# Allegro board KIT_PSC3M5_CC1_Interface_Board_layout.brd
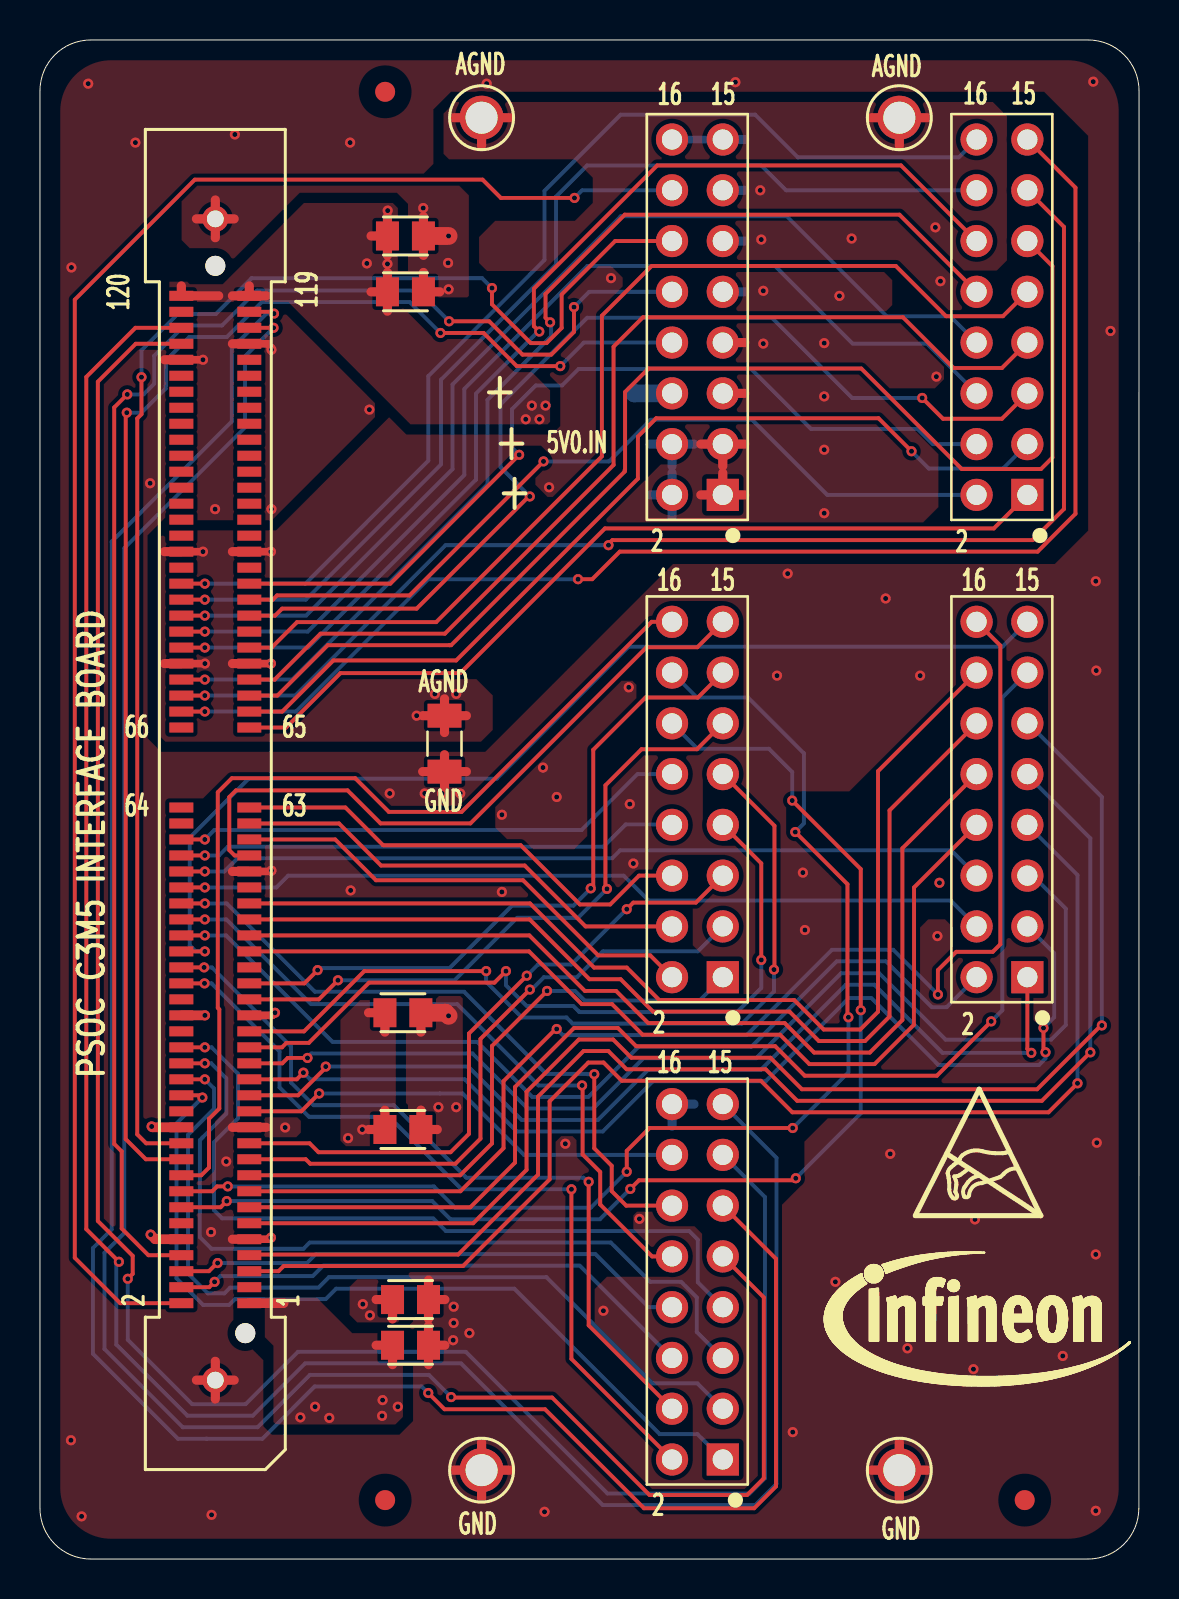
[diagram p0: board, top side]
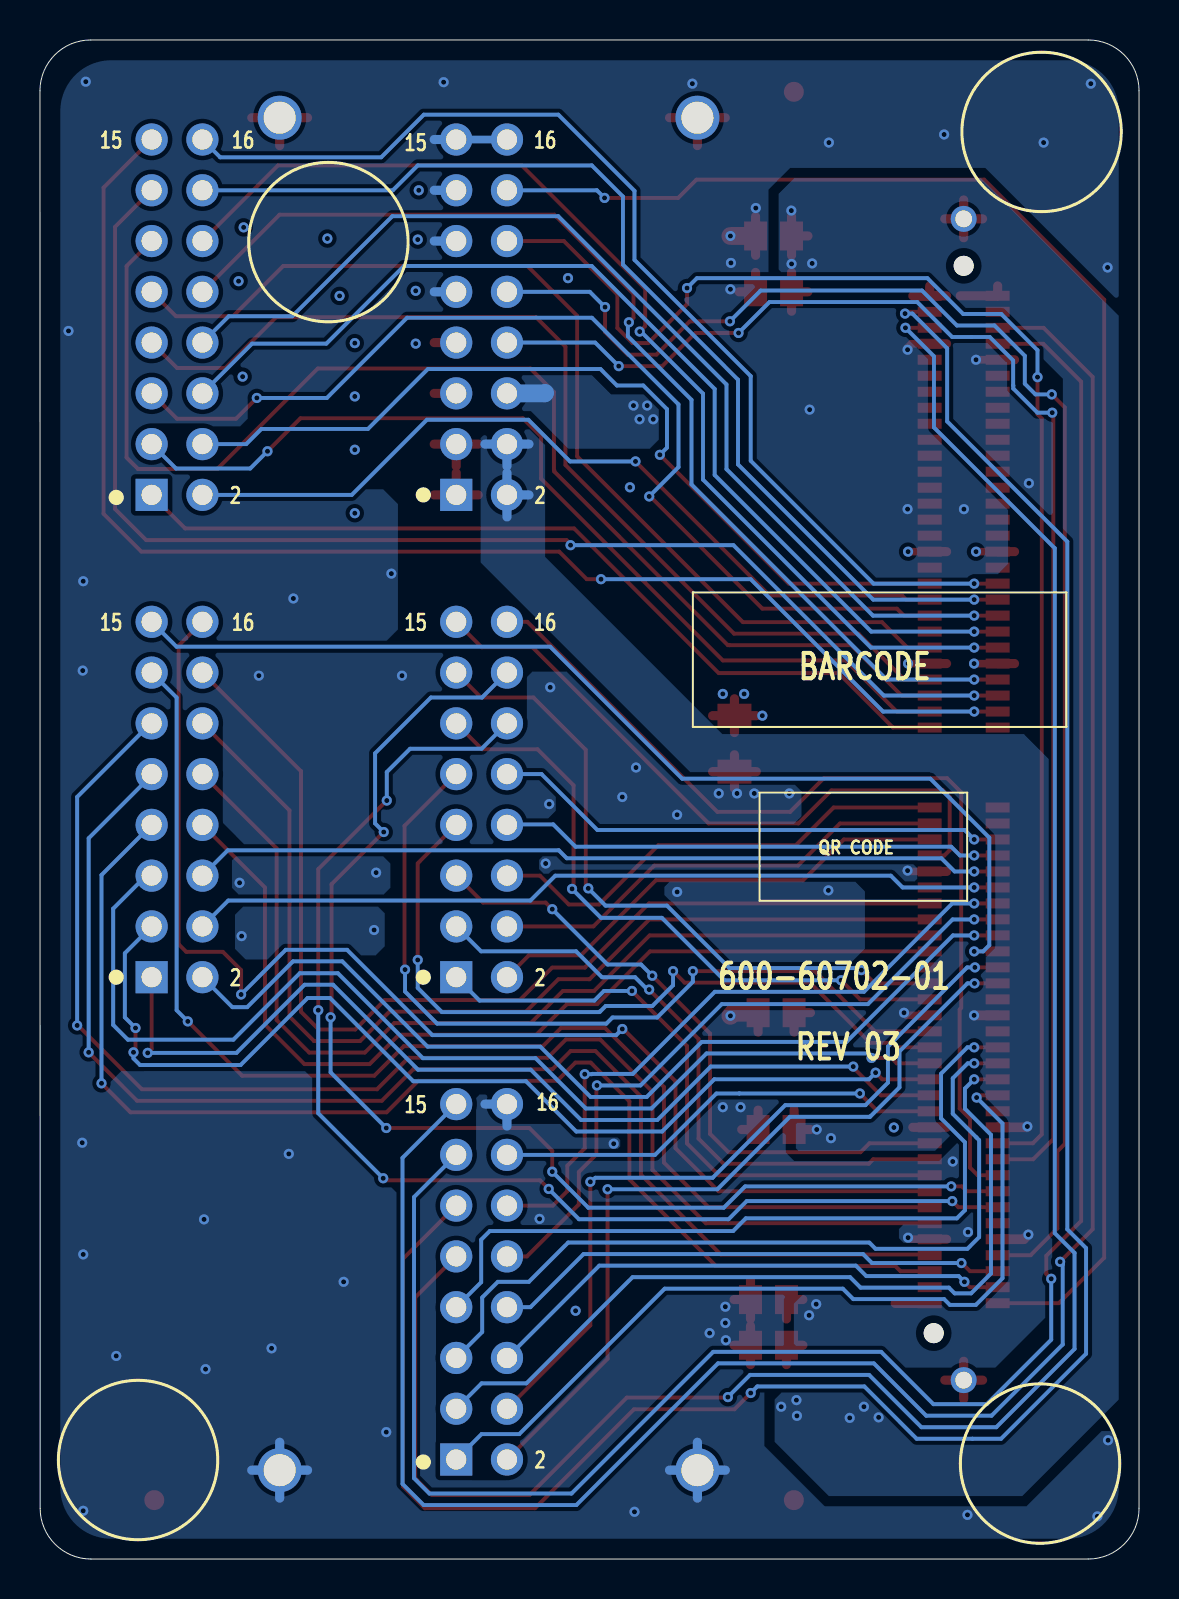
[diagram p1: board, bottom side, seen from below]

Outline 55 x 76 mm; copper layers: TOP, GND, GND1, BOTTOM. Coordinates in mm from the lower left corner of the outline.
Outline path: 0,73.46 0,2.54 arc(0.74,0.74) 2.54,0 52.45,0 arc(54.24,0.74) 54.99,2.54 55,73.46 arc(54.25,75.26) 52.46,76 2.54,76 arc(0.74,75.26) 0,73.46

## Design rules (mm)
constraint set DEFAULT: min track width 0.196

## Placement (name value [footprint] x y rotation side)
C1  0.1uF  [CAPC2012_0805N]  18.29 66.19 0 top
C2  0.1uF  [CAPC2012_0805N]  18.29 63.4 0 top
C3  0.1uF  [CAPC2012_0805N]  18.54 10.69 0 top
C4  0.1uF  [CAPC2012_0805N]  18.16 27.33 0 top
C5  0.1uF  [CAPC2012_0805N]  18.16 21.49 0 top
C6  0.1uF  [CAPC2012_0805N]  18.54 12.98 0 top
J1  HSEC8-160-01-L-DV-A-BL  [SAMTEC_HSEC8-160-01-L-DV-A-BL]  8.77 38 90 top
J2  HDR 8x2  [CTST254P2X08_W515]  34.17 4.98 90 top
J3  HDR 8x2  [CTST254P2X08_W515]  49.41 29.11 90 top
J4  HDR 8x2  [CTST254P2X08_W515]  34.17 29.11 90 top
J5  HDR 8x2  [CTST254P2X08_W515]  34.17 53.24 90 top
J6  HDR 8x2  [CTST254P2X08_W515]  49.41 53.24 90 top
NOREF  -  []  23.53 72.82 0 top
NOREF#2  -  []  -33.32 26.75 0 top
NOREF#3  -  []  7.07 12.8 90 top
NOREF#4  -  []  23.53 5.16 0 top
NOREF#5  -  []  5.27 71.52 0 top
NOREF#6  -  []  8.77 64.7 0 top
NOREF#7  -  [unnamed#2]  17.27 2.95 0 top
NOREF#8  -  []  124 82.91 0 top
NOREF#9  -  []  44.44 5.16 0 top
NOREF#10  -  []  0 2.54 0 top
NOREF#11  -  [unnamed#2]  17.27 73.41 0 top
NOREF#12  -  []  7.07 63.2 0 top
NOREF#13  -  []  -287.97 -199.2 0 top
NOREF#14  -  []  8.77 8.95 90 top
NOREF#15  -  []  166.42 292.69 0 top
NOREF#16  -  []  54.38 75.12 0 top
NOREF#17  -  []  2.54 0 90 top
NOREF#18  -  []  44.44 72.82 0 top
NOREF#19  -  []  7.07 41.6 90 top
NOREF#20  -  []  7.07 37.6 90 top
NOREF#21  -  []  8.77 8.95 90 top
NOREF#22  -  []  -32.82 -22.43 0 top
NOREF#23  -  []  5.27 4.47 90 top
NOREF#24  -  [unnamed#2]  49.28 2.95 0 top
R1  0 OHM  [RESC3216_1206N]  20.24 40.79 90 top
TP1  BLACK  [TPT_KEY_5011]  43 4.45 0 top
TP2  BLACK  [TPT_KEY_5011]  22.1 4.45 0 top
TP3  BLACK  [TPT_KEY_5011]  22.1 72.11 0 top
TP4  BLACK  [TPT_KEY_5011]  43 72.11 0 top

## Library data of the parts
C1-C6 = CAP-NP
J1 = SKT-120-ODD-EVEN-HSEC8-2SH-J
J2-J6 = PLG-16-ODD-EVEN-J
R1 = RES: User Part Number: Part No
TP1-TP4 = TP

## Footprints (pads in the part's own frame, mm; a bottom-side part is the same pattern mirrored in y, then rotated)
CAPC2012_0805N
  rect 1.15x1.45 smd: 1(-0.9,0) 2(0.9,0)
CTST254P2X08_W515
  rect 1.61x1.61 hole 1.01: 1(0,0)
  round 1.61 hole 1.01: 2(0,2.54) 3(2.54,0) 4(2.54,2.54) 5(5.08,0) 6(5.08,2.54) 7(7.62,0) 8(7.62,2.54) 9(10.16,0) 10(10.16,2.54) 11(12.7,0) 12(12.7,2.54) 13(15.24,0) 14(15.24,2.54) 15(17.78,0) 16(17.78,2.54)
RESC3216_1206N
  rect 1.2x1.7 smd: 1(-1.4,0) 2(1.4,0)
SAMTEC_HSEC8-160-01-L-DV-A-BL
  round 1 hole 1.27 unplated: (-26.7,-1.5) (26.7,0)
  rect 0.5x1.2 smd: 1(-25.2,-1.7) 2(-25.2,1.7) 3(-24.4,-1.7) 4(-24.4,1.7) 5(-23.6,-1.7) 6(-23.6,1.7) 7(-22.8,-1.7) 8(-22.8,1.7) 9(-22,-1.7) 10(-22,1.7) 11(-21.2,-1.7) 12(-21.2,1.7) 13(-20.4,-1.7) 14(-20.4,1.7) 15(-19.6,-1.7) 16(-19.6,1.7) 17(-18.8,-1.7) 18(-18.8,1.7) 19(-18,-1.7) 20(-18,1.7) 21(-17.2,-1.7) 22(-17.2,1.7) 23(-16.4,-1.7) 24(-16.4,1.7) 25(-15.6,-1.7) 26(-15.6,1.7) 27(-14.8,-1.7) 28(-14.8,1.7) 29(-14,-1.7) 30(-14,1.7) 31(-13.2,-1.7) 32(-13.2,1.7) 33(-12.4,-1.7) 34(-12.4,1.7) 35(-11.6,-1.7) 36(-11.6,1.7) 37(-10.8,-1.7) 38(-10.8,1.7) 39(-10,-1.7) 40(-10,1.7) 41(-9.2,-1.7) 42(-9.2,1.7) 43(-8.4,-1.7) 44(-8.4,1.7) 45(-7.6,-1.7) 46(-7.6,1.7) 47(-6.8,-1.7) 48(-6.8,1.7) 49(-6,-1.7) 50(-6,1.7) 51(-5.2,-1.7) 52(-5.2,1.7) 53(-4.4,-1.7) 54(-4.4,1.7) 55(-3.6,-1.7) 56(-3.6,1.7) 57(-2.8,-1.7) 58(-2.8,1.7) 59(-2,-1.7) 60(-2,1.7) 61(-1.2,-1.7) 62(-1.2,1.7) 63(-0.4,-1.7) 64(-0.4,1.7) 65(3.6,-1.7) 66(3.6,1.7) 67(4.4,-1.7) 68(4.4,1.7) 69(5.2,-1.7) 70(5.2,1.7) 71(6,-1.7) 72(6,1.7) 73(6.8,-1.7) 74(6.8,1.7) 75(7.6,-1.7) 76(7.6,1.7) 77(8.4,-1.7) 78(8.4,1.7) 79(9.2,-1.7) 80(9.2,1.7) 81(10,-1.7) 82(10,1.7) 83(10.8,-1.7) 84(10.8,1.7) 85(11.6,-1.7) 86(11.6,1.7) 87(12.4,-1.7) 88(12.4,1.7) 89(13.2,-1.7) 90(13.2,1.7) 91(14,-1.7) 92(14,1.7) 93(14.8,-1.7) 94(14.8,1.7) 95(15.6,-1.7) 96(15.6,1.7) 97(16.4,-1.7) 98(16.4,1.7) 99(17.2,-1.7) 100(17.2,1.7) 101(18,-1.7) 102(18,1.7) 103(18.8,-1.7) 104(18.8,1.7) 105(19.6,-1.7) 106(19.6,1.7) 107(20.4,-1.7) 108(20.4,1.7) 109(21.2,-1.7) 110(21.2,1.7) 111(22,-1.7) 112(22,1.7) 113(22.8,-1.7) 114(22.8,1.7) 115(23.6,-1.7) 116(23.6,1.7) 117(24.4,-1.7) 118(24.4,1.7) 119(25.2,-1.7) 120(25.2,1.7)
  round 1.3 hole 0.84: SH1(-29.05,0) SH2(29.05,0)
TPT_KEY_5011
  round 2.2 hole 1.6: 1(0,0)
unnamed#2
  round 1 smd: (0,0)

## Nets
+3V3_OUT: C1.1 C2.1 C3.1 J1.1 J1.119 J1.120 J5.6
+5V0_IN: C4.1 C5.1 C6.1 J1.10 J1.24 J1.38 J5.2 J5.4
AGND: J1.73 J1.74 J1.87 J1.88 J5.1 J5.3 J5.5 J5.7 R1.2 TP3.1(TP) TP4.1(TP)
GND_SIGNAL: C1.2 C2.2 C3.2 C4.2 C5.2 C6.2 J1.9 J1.23 J1.37 J1.55 J1.112 J1.113 J1.SH1 J1.SH2 J2.16 J5.9 J5.11 J5.13 J5.15 J5.16 R1.1 TP1.1(TP) TP2.1(TP)
A0: J1.65 J6.1
A1: J1.67 J6.3
A2: J1.79 J6.5
A3: J1.71 J6.7
A4: J1.75 J6.9
A5: J1.69 J6.11
A6: J1.70 J6.13
A7: J1.68 J6.15
B0: J1.81 J6.2
B1: J1.83 J6.4
B2: J1.78 J6.6
B3: J1.80 J6.8
B4: J1.72 J6.10
B5: J1.76 J6.12
B6: J1.82 J6.14
B7: J1.84 J6.16
P00: J1.28 J2.1
P01: J1.30 J2.3
P10: J1.32 J2.5
P11: J1.34 J2.7
P12: J1.115 J2.9
P13: J1.117 J2.11
P20: J1.114 J2.13
P21: J1.116 J2.15
P22: J1.42 J2.2
P23: J1.44 J2.4
P30: J1.4 J2.6
P31: J1.6 J2.8
P32: J1.50 J2.10
P33: J1.52 J2.12
P40: J1.25 J2.14
P41: J1.27 J3.1
P42: J1.29 J3.3
P43: J1.31 J3.5
P44: J1.5 J3.7
P45: J1.7 J3.9
P46: J1.11 J3.11
P47: J1.13 J3.13
P50: J1.46 J3.15
P51: J1.48 J3.2
P52: J1.54 J3.4
P53: J1.56 J3.6
P60: J1.45 J3.8
P61: J1.47 J3.10
P62: J1.49 J3.12
P63: J1.51 J3.14
P70: J1.15 J3.16
P71: J1.17 J4.1
P72: J1.19 J4.3
P73: J1.21 J4.5
P74: J1.33 J4.7
P75: J1.35 J4.9
P76: J1.39 J4.11
P77: J1.41 J4.13
P80: J1.57 J4.15
P81: J1.59 J4.2
P82: J1.61 J4.4
P83: J1.63 J4.6
P84: J1.58 J4.8
P85: J1.60 J4.10
P90: J1.14 J4.12
P91: J1.16 J4.14
P92: J1.18 J4.16
P93: J1.20 J5.8
P94: J1.8 J5.10
P95: J1.22 J5.12
XRES: J1.2 J5.14

Pads without a net: J1 3 12 26 36 40 43 53 62 64 66 77 85 86 89 90 91 92 93 94 95 96 97 98 99 100 101 102 103 104 105 106 107 108 109 110 111 118

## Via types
v1: diameter 0.508, hole 0.254, TOP to BOTTOM, 200 vias

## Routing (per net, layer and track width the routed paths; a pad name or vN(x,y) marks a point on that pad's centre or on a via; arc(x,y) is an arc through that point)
+3V3_OUT: length 15.5
  TOP w0.457: 17.39,65.22 C1.1 ; C1.1 16.57,66.19 ; C1.1 17.39,67.16 ; 17.39,62.43 C2.1 ; C2.1 17.39,64.37 ; C2.1 16.57,63.4 ; 9.63,63.2 J1.119 ; J1.119 10.47,63.69 ; J1.119 11.32,63.2 ; 16.82,10.69 C3.1 17.64,9.73 ; 8.94,63.2 J1.120 7.07,63.69
  TOP w0.483: J1.1 12.19,12.8
  BOTTOM w0.889: J5.6 29.74,58.32 29.72,58.34
  vias: v1(13.03,7.09) v1(13.77,7.62) v1(14.48,7.06) v1(16.36,64.82) v1(17.14,7.95) v1(17.12,7.16) v1(17.4,67.46) v1(17.39,64.8) v1(17.91,7.62) v1(24.31,57.02) v1(24.61,57.71) v1(24.99,57.02) v1(25.3,57.71)
+5V0_IN: length 16.3
  TOP w0.457: 17.26,26.36 C4.1 16.44,27.33 ; 17.64,12.01 C6.1 16.82,12.98 ; 16.44,21.49 C5.1 17.26,22.46
  TOP w0.483: J1.38 v1(8.26,27.2) ; J1.10 5.77,16 v1(5.54,16.23) ; v1(5.59,21.64) 5.63,21.6 J1.24
  BOTTOM w0.457: 30.53,53.24 J5.2 ; J5.2 31.63,52.14 ; J5.2 31.63,54.34 ; J5.4 32.73,55.78 ; J5.4 31.63,54.68 ; J5.4 30.53,55.78
  vias: v1(15.42,21.06) v1(16.13,21.49) v1(16.15,12.75) v1(16.51,12.19)
AGND: length 76.6
  TOP w0.381: J1.74 v1(8.26,44.8) ; J1.87 v1(11.56,50.4) ; J1.73 v1(11.56,44.8) ; J1.88 v1(8.16,50.4)
  TOP w0.457: J5.3 35.27,55.78 ; J5.3 33.07,55.78 ; J5.3 34.17,54.68 ; J5.7 35.27,60.86 ; 41.61,72.11 TP4.1 ; TP4.1 43,70.72 ; TP4.1 44.4,72.11 ; J5.5 35.27,58.32 ; R1.2 21.34,42.19 ; R1.2 19.15,42.19 ; R1.2 20.24,41.35 ; R1.2 20.24,43.04 ; J5.1 35.27,53.24 ; J5.1 33.07,53.24 ; J5.1 34.17,54.34 ; TP3.1 23.49,72.11 ; TP3.1 20.7,72.11 ; TP3.1 22.1,70.72 ; 9.63,44.8 J1.73 ; 6.23,50.4 J1.88 ; 6.23,44.8 J1.74 ; 9.63,50.4 J1.87
  GND w0.457: J5.3 35.27,55.78 ; J5.3 33.07,55.78 ; J5.3 34.17,56.88 ; J5.3 34.17,54.68 ; J5.1 35.27,53.24 ; J5.1 34.17,54.34 ; J5.1 34.17,52.14 ; J5.1 33.07,53.24 ; 34.17,57.22 J5.5 ; J5.5 34.17,59.42 ; J5.5 33.07,58.32 ; J5.5 35.27,58.32 ; J5.7 34.17,61.96 ; J5.7 35.27,60.86 ; J5.7 34.17,59.76 ; J5.7 33.07,60.86 ; TP4.1 44.4,72.11 ; TP4.1 41.61,72.11 ; TP4.1 43,70.72 ; 22.1,70.72 TP3.1 ; TP3.1 20.7,72.11 ; TP3.1 23.49,72.11
  GND1 w0.457: 34.17,59.76 J5.7 ; J5.7 35.27,60.86 ; J5.7 33.07,60.86 ; J5.7 34.17,61.96 ; J5.3 35.27,55.78 ; J5.3 34.17,56.88 ; J5.3 34.17,54.68 ; J5.3 33.07,55.78 ; TP4.1 44.4,72.11 ; TP4.1 41.61,72.11 ; TP4.1 43,70.72 ; 33.07,58.32 J5.5 ; J5.5 34.17,57.22 ; J5.5 34.17,59.42 ; J5.5 35.27,58.32 ; 34.17,52.14 J5.1 ; J5.1 33.07,53.24 ; J5.1 34.17,54.34 ; J5.1 35.27,53.24
  vias: v1(18.85,42.19) v1(19.76,43.28) v1(20.83,43.28) v1(25.48,53.62) v1(28.57,64.08) v1(36.04,68.48) v1(36.09,66.01) v1(36.2,63.45) v1(36.2,60.81) v1(39.24,60.83) v1(39.24,58.17) v1(39.24,55.5) v1(39.24,52.32) v1(40.01,63.2) v1(40.61,66.07) v1(44.81,66.62) v1(44.86,59.16) v1(45.06,63.93)
GND_SIGNAL: length 114.9
  TOP w0.381: v1(11.56,16.08) 11.48,16 J1.9 ; v1(11.76,27.33) 11.63,27.2 J1.37 ; v1(11.58,34.44) 11.54,34.4 J1.55 ; v1(11.58,60.5) 11.58,60.6 11.39,60.8 J1.113 ; J1.112 v1(8.16,60)
  TOP w0.457: 9.63,34.4 J1.55 ; 8.77,66.1 J1.SH2 ; J1.SH2 7.83,67.05 ; J1.SH2 9.72,67.05 ; J1.SH2 8.77,68 ; J1.SH1 9.72,8.95 ; J1.SH1 8.77,8 ; J1.SH1 8.77,9.9 ; J1.SH1 7.83,8.95 ; 19.19,64.37 C2.2 20.01,63.4 ; 41.61,4.45 TP1.1 ; TP1.1 43,3.05 ; TP1.1 44.4,4.45 ; TP1.1 43,5.84 ; R1.1 21.34,39.39 ; R1.1 20.24,40.24 ; R1.1 20.24,38.55 ; R1.1 19.15,39.39 ; C3.2 19.44,11.66 ; C3.2 20.26,10.69 ; C3.2 19.44,9.73 ; 11.32,21.6 J1.23 9.63,21.6 ; 19.19,65.22 C1.2 19.19,67.16 ; TP2.1 23.49,4.45 ; TP2.1 22.1,5.84 ; TP2.1 20.7,4.45 ; TP2.1 22.1,3.05 ; C6.2 20.26,12.98 ; C6.2 19.44,13.95 ; C6.2 19.44,12.01 ; 9.63,16 J1.9 ; 19.06,26.36 C4.2 ; 9.63,60.8 J1.113 ; 19.88,21.49 C5.2 19.06,22.46 ; 6.23,60 J1.112
  TOP w0.889: v1(20.45,27.18) 20.29,27.33 C4.2 ; C1.2 v1(20.45,66.19)
  GND w0.457: J2.16 32.73,22.76 ; J2.16 30.53,22.76 ; J2.16 31.63,21.66 ; J2.16 31.63,23.86 ; 8.77,66.1 J1.SH2 ; J1.SH2 8.77,68 ; J1.SH2 9.72,67.05 ; J1.SH2 7.83,67.05 ; 41.61,4.45 TP1.1 ; TP1.1 43,3.05 ; TP1.1 43,5.84 ; TP1.1 44.4,4.45 ; 7.83,8.95 J1.SH1 ; J1.SH1 9.72,8.95 ; J1.SH1 8.77,9.9 ; J1.SH1 8.77,8 ; TP2.1 22.1,5.84 ; TP2.1 23.49,4.45 ; TP2.1 22.1,3.05 ; TP2.1 20.7,4.45
  GND1 w0.457: J1.SH1 8.77,9.9 ; J1.SH1 7.83,8.95 ; J1.SH1 8.77,8 ; J1.SH1 9.72,8.95 ; 7.83,67.05 J1.SH2 ; J1.SH2 8.77,68 ; J1.SH2 9.72,67.05 ; J1.SH2 8.77,66.1 ; TP2.1 23.49,4.45 ; TP2.1 20.7,4.45 ; TP2.1 22.1,3.05 ; TP2.1 22.1,5.84 ; 30.53,22.76 J2.16 ; J2.16 32.73,22.76 ; J2.16 31.63,23.86 ; J2.16 31.63,21.66 ; 43,3.05 TP1.1 ; TP1.1 41.61,4.45 ; TP1.1 44.4,4.45 ; TP1.1 43,5.84
  BOTTOM w0.381: J5.15 J5.16
  BOTTOM w0.457: 41.61,4.45 TP1.1 ; TP1.1 43,5.84 ; TP1.1 43,3.05 ; TP1.1 44.4,4.45 ; J5.15 35.27,71.02 ; 32.73,22.76 J2.16 31.63,21.66 ; J5.13 35.27,68.48 ; 22.1,3.05 TP2.1 ; TP2.1 23.49,4.45 ; TP2.1 22.1,5.84 ; TP2.1 20.7,4.45 ; J5.11 35.27,65.94 ; J5.9 35.27,63.4
  vias: v1(1.55,5.94) v1(1.57,64.62) v1(2.08,2.13) v1(2.41,73.81) v1(4.78,70.87) v1(5.51,53.82) v1(8.56,16.36) v1(8.59,2.21) v1(8.76,52.53) v1(9.32,19.89) v1(9.75,71.27) v1(11.58,52.53) v1(12.27,21.59) v1(15.52,70.87) v1(15.54,33.45) v1(16.48,57.51) v1(17.5,38.3) v1(19.18,67.59) v1(19.25,38.3) v1(19.94,22.61) v1(20.12,38.3) v1(20.42,64.85) v1(20.45,63.53) v1(20.7,12.62) v1(20.7,11.81) v1(20.68,10.95) v1(20.83,22.61) v1(21.03,38.3) v1(21.49,11.3) v1(22.35,73.81) v1(23.11,37.24) v1(23.11,33.38) v1(25.17,39.6) v1(25.25,2.36) v1(25.86,38.13) v1(26.29,20.78) v1(28.19,12.42) v1(29.46,43.61) v1(29.51,37.77) v1(29.69,34.8) v1(30,17.02) v1(34.8,73.89) v1(36.88,44.2) v1(37.41,49.3) v1(37.67,6.35) v1(38.18,34.34) v1(38.28,31.47) v1(39.8,13.87) v1(42.32,48.06) v1(42.55,20.27) v1(43.41,10.54) v1(44.04,44.2) v1(44.91,31.17) v1(45.01,33.83) v1(46.71,9.5) v1(46.79,16.99) v1(51.18,10.16) v1(52.7,73.91) v1(52.83,48.92) v1(52.83,15.24) v1(52.83,2.41) v1(52.86,44.45) v1(52.88,20.83) v1(53.57,61.44)
A0: length 43.8
  TOP w0.196: J1.65 12.31,41.6 15.04,44.32 21.03,44.32 28.27,51.56 47.73,51.56 J6.1
A1: length 47.8
  TOP w0.196: v1(43.61,55.42) 41.96,57.07 30.84,57.07 29.92,56.16 29.92,54.05 20.83,44.96 14.68,44.96 12.12,42.4 J1.67
  BOTTOM w0.196: v1(43.61,55.42) 44.48,54.56 48.19,54.56 J6.3
A2: length 52.5
  TOP w0.196: J1.79 11.77,47.2 12.12,47.55 18.85,47.55 24.46,53.16 v1(24.51,53.16) ; J6.5 48.14,57.05 45.19,57.05 v1(44.15,58.09)
  BOTTOM w0.196: v1(44.15,58.09) 40.64,58.09 36.63,62.1 27.38,62.1 23.05,57.77 23.05,54.63 v1(24.51,53.16)
A3: length 51.5
  TOP w0.196: J6.7 48.14,59.59 45.72,59.59 43.18,62.13 30.18,62.13 28.7,60.66 28.7,54.74 20.26,46.3 14.04,46.3 11.74,44 J1.71
A4: length 52.5
  TOP w0.196: J1.75 11.59,45.6 12.86,46.87 19.82,46.87 28.12,55.17 28.12,62.2 30.61,64.69 42.82,64.69 45.34,62.18 48.19,62.18 J6.9
A5: length 63
  TOP w0.196: J6.11 50.66,64.69 50.66,55.11 50.09,54.53 46.13,54.53 41.1,59.56 30.45,59.56 29.28,58.39 29.28,54.5 29.26,54.48 29.26,54.41 20.57,45.72 20.5,45.72 14.4,45.72 11.88,43.2 J1.69
A6: length 64.8
  TOP w0.196: v1(28.45,50.72) 28.45,50.78 28.64,50.98 49.68,50.98 51.24,52.53 51.24,66.65 J6.13 ; J1.70 v1(8.25,43.2)
  BOTTOM w0.196: v1(28.45,50.72) 20.29,50.72 12.77,43.2 v1(8.25,43.2)
A7: length 68.6
  TOP w0.196: J1.68 v1(8.25,42.4) ; J6.15 51.82,68.61 51.82,52.3 49.92,50.4 29.01,50.4 27.63,49.02 v1(26.92,49.02)
  BOTTOM w0.196: v1(26.92,49.02) 19.43,49.02 12.81,42.4 v1(8.25,42.4)
B0: length 41.7
  TOP w0.196: v1(25.2,54.91) 18.49,48.21 11.86,48.21 11.65,48 J1.81
  BOTTOM w0.196: v1(25.2,54.91) 28.47,54.91 30.56,57 35.64,57 39.39,53.24 J6.2
B1: length 44.2
  TOP w0.196: v1(23.98,55.24) 17.53,48.8 J1.83
  BOTTOM w0.196: v1(23.98,55.24) 23.62,55.6 23.62,57.53 24.81,58.71 26.13,58.71 26.95,59.54 35.59,59.54 38.58,56.54 43.92,56.54 44.68,55.78 J6.4
B2: length 52.5
  TOP w0.196: J1.78 v1(8.25,46.4)
  BOTTOM w0.196: J6.6 44.38,60.81 40.67,60.81 36.78,64.69 27.39,64.69 21.23,58.54 21.23,54.23 13.4,46.4 v1(8.25,46.4)
B3: length 53.2
  TOP w0.196: J1.80 v1(8.25,47.2)
  BOTTOM w0.196: J6.8 45.55,62.18 42.37,62.18 37.36,67.18 29.06,67.18 20.64,58.76 20.64,54.53 13.32,47.2 v1(8.25,47.2)
B4: length 55.1
  TOP w0.196: J1.72 v1(8.25,44) ; J6.10 43.01,67.26 29.26,67.26 25.3,63.3 25.3,62.1 v1(25.53,61.87)
  BOTTOM w0.196: v1(8.25,44) 12.63,44 22.4,53.76 22.4,58 25.58,61.18 25.58,61.82 v1(25.53,61.87)
B5: length 55.5
  TOP w0.196: J1.76 v1(8.25,45.6) ; v1(24.99,61.41) 24.71,61.68 24.71,63.55 30.89,69.72 43.09,69.72 J6.12
  BOTTOM w0.196: v1(24.99,61.41) 24.92,61.41 21.82,58.31 21.82,54 13.42,45.6 v1(8.25,45.6)
B6: length 53.8
  TOP w0.196: J1.82 v1(8.25,48)
  BOTTOM w0.196: v1(8.25,48) 13.3,48 20.07,54.77 20.07,59 25.82,64.76 25.82,68.17 27.38,69.72 36.09,69.72 37.34,68.48 J6.14
B7: length 55.3
  TOP w0.196: J1.84 v1(8.25,48.8)
  BOTTOM w0.196: J6.16 45.98,70.13 37.92,70.13 35.79,72.26 29.06,72.26 25.25,68.45 25.25,65 19.43,59.18 19.43,54.95 13.29,48.8 v1(8.25,48.8)
P00: length 42.4
  TOP w0.196: J1.28 8.02,23.2 v1(8.13,23.09)
  BOTTOM w0.196: J2.1 32.9,6.25 31.01,6.25 23.74,13.53 14.82,13.53 14.3,13 9.75,13 9.47,12.71 8.16,12.71 6.83,14.05 6.83,21.79 v1(8.13,23.09)
P01: length 41.9
  TOP w0.196: J1.30 v1(8.25,24)
  BOTTOM w0.196: v1(8.25,24) 8.71,23.54 8.71,22.53 7.41,21.23 7.41,14.29 8.4,13.29 9.23,13.29 9.51,13.58 13.93,13.58 14.46,14.1 25.34,14.1 30.66,8.79 32.9,8.79 J2.3
P10: length 41
  TOP w0.196: J1.32 v1(8.25,24.8)
  BOTTOM w0.196: v1(8.25,24.8) 8.57,24.8 9.32,24.05 9.32,22.28 8.14,21.09 8.14,21.09 8,20.95 8,16.1 8.59,15.52 13.18,15.52 13.5,15.83 28.57,15.83 30.53,13.87 32.08,13.87 32.87,13.08 32.87,11.36 J2.5
P11: length 39.4
  TOP w0.196: J1.34 v1(8.25,25.6)
  BOTTOM w0.196: v1(8.25,25.6) 8.59,25.6 9.91,24.28 9.91,22.05 8.71,20.85 8.71,17.45 9.12,17.04 19.68,17.04 20.31,16.41 32.49,16.41 32.92,15.98 32.92,13.85 J2.7
P12: length 106.3
  TOP w0.196: J1.115 v1(11.69,61.6) ; J2.9 36.22,13.09 36.22,4.04 35.38,3.2 30.51,3.2 25.63,8.08 20.6,8.08 v1(20.57,8.1)
  BOTTOM w0.196: v1(11.69,61.6) 10.26,60.17 10.26,56.62 4.22,50.57 4.22,16.31 3.23,15.32 3.23,10.51 7.14,6.59 10.89,6.59 13.51,9.21 19.46,9.21 v1(20.57,8.1)
P13: length 112.4
  TOP w0.196: J2.11 36.83,15.02 36.83,3.63 35.74,2.54 30.23,2.54 25.27,7.49 20.24,7.49 v1(19.43,8.31) ; J1.117 11.62,62.4 11.7,62.31 v1(11.71,62.31)
  BOTTOM w0.196: v1(11.71,62.31) 11.34,62.31 9.6,60.57 9.6,56.92 3.59,50.9 3.59,16.5 2.65,15.56 2.65,10.27 6.9,6.02 8.34,6.02 8.34,6.02 11.13,6.02 13.75,8.64 19.1,8.64 v1(19.43,8.31)
P20: length 108.3
  TOP w0.196: J1.114 4.79,60.8 2.9,58.9 2.9,16.91 4.64,15.17 4.64,14.27 v1(4.39,14.02)
  BOTTOM w0.196: J2.13 36.28,18.11 36.28,4.05 35.51,3.28 28.4,3.28 21.31,10.37 12.91,10.37 10.29,7.75 7.62,7.75 4.39,10.97 v1(4.39,14.02)
P21: length 114
  TOP w0.196: J1.116 4.78,61.6 2.32,59.14 2.32,16.5 v1(3.95,14.87)
  BOTTOM w0.196: v1(3.95,14.87) 3.82,14.74 3.82,10.73 7.38,7.17 10.65,7.17 13.27,9.79 21.07,9.79 28.16,2.7 35.8,2.7 36.86,3.76 36.86,20.07 J2.15
P22: length 40.4
  TOP w0.196: v1(26.59,18.5) 26.59,10.01 J2.2 ; J1.42 v1(8.23,28.8)
  BOTTOM w0.196: v1(8.23,28.8) 8.59,28.8 11.99,25.4 11.99,23.59 13.45,22.13 13.48,22.13 13.49,22.12 17.47,22.12 21.1,18.5 v1(26.59,18.5)
P23: length 39
  TOP w0.196: v1(27.46,18.87) 27.46,11.69 J2.4 ; J1.44 v1(8.21,29.6)
  BOTTOM w0.196: v1(8.21,29.6) 8.6,29.6 12.57,25.64 12.57,23.83 13.69,22.71 17.7,22.71 21.34,19.08 27.2,19.08 27.41,18.87 v1(27.46,18.87)
P30: length 26.9
  TOP w0.196: J1.4 8.47,13.6 v1(8.74,13.87)
  BOTTOM w0.196: v1(8.74,13.87) 9.02,14.16 13.65,14.16 14.17,14.68 27.01,14.68 J2.6
P31: length 26
  TOP w0.196: J1.6 8.45,14.4 8.86,14.81 v1(8.89,14.81)
  BOTTOM w0.196: J2.8 30.45,12.6 27.8,15.26 13.81,15.26 13.36,14.81 v1(8.89,14.81)
P32: length 34.5
  TOP w0.196: J2.10 30.63,15.14 28.03,17.74 28.03,19.36 27.15,20.24 27.15,23.67 v1(27.13,23.69) ; J1.50 v1(8.25,32)
  BOTTOM w0.196: v1(8.25,32) 9.33,32 13.57,27.76 20.88,27.76 24.95,23.69 v1(27.13,23.69)
P33: length 33.7
  TOP w0.196: v1(27.74,24.26) 27.74,20.55 28.61,19.67 28.61,18.4 29.34,17.68 J2.12 ; J1.52 v1(8.25,32.8)
  BOTTOM w0.196: v1(27.74,24.26) 27.38,24.26 27.37,24.27 25.33,24.27 21.23,28.38 13.76,28.38 9.34,32.8 v1(8.25,32.8)
P40: length 22.8
  TOP w0.196: J1.25 13.08,22.4 v1(13.97,23.29)
  BOTTOM w0.196: v1(13.97,23.29) 20,23.29 21.15,23.29 24.22,20.22 J2.14
P41: length 48.9
  TOP w0.196: v1(49.61,25.32) 49.41,25.52 J3.1 ; J1.27 12.91,23.2 14.3,24.59 v1(14.3,24.64)
  BOTTOM w0.196: v1(49.61,25.32) 45.16,25.32 41.76,28.73 40.33,28.73 36.08,24.48 30.44,24.48 27.92,21.97 24.1,21.97 21.43,24.64 v1(14.3,24.64)
P42: length 52.9
  TOP w0.196: v1(50.22,26.57) 50.22,25.45 v1(50.32,25.35) ; J1.29 12.85,24 v1(13.18,24.33)
  BOTTOM w0.196: v1(50.32,25.35) 50.32,25.04 49.99,24.71 44.96,24.71 41.6,28.07 40.48,28.07 36.32,23.9 30.68,23.9 28.16,21.39 23.87,21.39 21.25,24 13.51,24 v1(13.18,24.33) ; J3.3 50.75,30.31 50.75,27.1 v1(50.22,26.57)
P43: length 55.1
  TOP w0.196: J1.31 12.13,24.8 12.4,25.07 v1(13.39,25.07)
  BOTTOM w0.196: J3.5 49.68,34.19 51.33,32.54 51.33,26.72 50.6,25.98 45.32,25.98 41.99,29.31 40.09,29.31 35.84,25.06 30.2,25.06 27.68,22.54 24.39,22.54 21.64,25.3 13.58,25.3 13.39,25.1 v1(13.39,25.07)
P44: length 63.7
  TOP w0.196: v1(51.92,23.8) 50.47,22.35 37.65,22.35 36.07,23.93 29.11,23.93 28.2,24.84 27.44,24.84 25.5,22.9 25.5,18.99 21.17,14.66 12.19,14.66 11.94,14.4 J1.5
  BOTTOM w0.196: v1(51.92,23.8) 51.92,34.22 J3.7
P45: length 65.9
  TOP w0.196: J1.7 10.51,15.23 20.93,15.23 24.93,19.23 24.93,23.14 27.2,25.42 28.44,25.42 29.35,24.5 36.31,24.5 37.89,22.93 50.14,22.93 v1(52.56,25.35)
  BOTTOM w0.196: v1(52.56,25.35) 52.56,36.06 49.41,39.21 J3.9
P46: length 67.8
  TOP w0.196: J1.11 21.68,16.8 24.35,19.47 24.35,23.38 26.96,25.99 28.68,25.99 29.59,25.08 36.55,25.08 38.13,23.5 49.9,23.5 53.09,26.7 v1(53.14,26.7)
  BOTTOM w0.196: J3.11 49.45,41.81 53.14,38.13 v1(53.14,26.7)
P47: length 63.4
  TOP w0.196: J1.13 21.54,17.6 23.77,19.84 23.77,23.62 26.72,26.57 28.92,26.57 29.83,25.66 36.79,25.66 38.27,24.18 44.88,24.18 v1(47.6,26.9)
  BOTTOM w0.196: v1(47.6,26.9) 48.16,27.46 48.16,43.1 J3.13
P50: length 53.8
  TOP w0.196: J1.46 v1(8.25,30.4)
  BOTTOM w0.196: v1(8.25,30.4) 7.8,30.4 7.49,30.71 7.49,36.09 10.44,39.04 22.86,39.04 29.46,45.64 48.16,45.64 J3.15
P51: length 47.5
  TOP w0.196: J1.48 v1(8.25,31.2)
  BOTTOM w0.196: v1(8.25,31.2) 9.31,31.2 14.64,25.87 21.88,25.87 24.63,23.12 27.44,23.12 29.96,25.63 35.6,25.63 39.87,29.9 42.33,29.9 44.63,27.61 45.37,27.61 J3.2
P52: length 41.1
  TOP w0.196: J1.54 v1(8.25,33.6)
  BOTTOM w0.196: v1(8.25,33.6) 11.83,33.6 12.42,34.19 29.21,34.19 30.45,32.94 45.57,32.94 J3.4
P53: length 40.8
  TOP w0.196: J1.56 v1(8.25,34.4)
  BOTTOM w0.196: J3.6 45.6,35.46 29.03,35.46 28.63,35.06 9.89,35.06 9.23,34.4 v1(8.25,34.4)
P60: length 47.7
  TOP w0.196: J1.45 24.47,30.4 27.11,27.76 28.63,27.76 30.15,26.23 37.03,26.23 38.5,24.76 41.76,24.76 43.73,26.73 43.73,28.49 43.74,28.5 43.74,33.6 J3.8
P61: length 49.6
  TOP w0.196: J1.47 24.49,31.2 27.27,28.42 28.83,28.42 30.44,26.81 37.27,26.81 38.74,25.34 41.52,25.34 43.15,26.97 43.15,35.56 J3.10
P62: length 51.5
  TOP w0.196: J1.49 24.5,32 27.5,29.01 29.06,29.01 30.68,27.39 37.51,27.39 38.98,25.92 41.29,25.92 42.51,27.14 42.51,37.45 J3.12
P63: length 53.5
  TOP w0.196: J3.14 41.94,39.42 41.94,27.38 41.05,26.49 39.22,26.49 37.74,27.97 30.99,27.97 29.36,29.59 27.73,29.59 24.52,32.8 J1.51
P70: length 64.1
  TOP w0.196: J3.16 48.06,45.7 48.06,30.76 47.68,30.38 45.85,30.38 44.93,29.46 v1(44.93,28.24) ; J1.15 21.04,18.4 23.2,20.55 23.2,23.91 25.81,26.52 v1(25.86,26.52)
  BOTTOM w0.196: v1(44.93,28.24) 42.7,30.48 39.63,30.48 35.36,26.21 26.16,26.21 v1(25.86,26.52)
P71: length 31.1
  TOP w0.196: v1(25.37,28.42) 22.62,25.67 22.62,20.79 21.03,19.2 J1.17
  BOTTOM w0.196: v1(25.37,28.42) 26.77,28.42 27.25,27.94 33,27.94 J4.1
P72: length 31.6
  TOP w0.196: J1.19 13.3,20 13.52,19.78 20.79,19.78 22.04,21.03 22.04,26.02 v1(24.51,28.49)
  BOTTOM w0.196: v1(24.51,28.49) 24.6,28.49 25.22,29.11 26.87,29.11 28.17,30.4 32.92,30.4 J4.3
P73: length 32.6
  TOP w0.196: v1(29.36,32.51) 29.69,32.84 32.82,32.84 J4.5 ; v1(24.36,29.18) 21.47,26.29 21.47,21.27 20.55,20.35 13.94,20.35 13.49,20.8 J1.21
  BOTTOM w0.196: v1(24.36,29.18) 24.92,29.74 26.59,29.74 v1(29.36,32.51)
P74: length 37.9
  TOP w0.196: J4.7 36.09,34.8 v1(36.09,29.97) ; v1(23.32,29.41) 22.74,28.84 16.47,28.84 13.45,25.82 12.33,25.82 12.11,25.6 J1.33
  BOTTOM w0.196: v1(23.32,29.41) 23.32,28.7 24.35,27.67 26.68,27.67 26.97,27.39 26.99,27.39 27.02,27.36 34.88,27.36 36.09,28.57 v1(36.09,29.97)
P75: length 41.5
  TOP w0.196: J4.9 36.75,36.68 36.75,29.51 v1(36.73,29.49) ; v1(22.33,29.41) 16.23,29.41 13.21,26.4 J1.35
  BOTTOM w0.196: v1(36.73,29.49) 36.73,28.39 35.12,26.79 26.65,26.79 26.35,27.09 24.11,27.09 22.33,28.88 v1(22.33,29.41)
P76: length 32.6
  TOP w0.196: J1.39 13.95,28 v1(14.91,28.96) ; J4.11 32.87,40.51 30.1,40.51 28.3,38.71 28.3,33.6 v1(28.37,33.53)
  BOTTOM w0.196: v1(28.37,33.53) 26.92,32.08 23.88,32.08 20.75,28.96 v1(14.91,28.96)
P77: length 34.1
  TOP w0.196: J4.13 32.92,43.1 30.3,43.1 27.69,40.49 27.69,33.68 v1(27.56,33.55) ; v1(13.89,29.46) 13.23,28.8 J1.41
  BOTTOM w0.196: v1(13.89,29.46) 14,29.57 20.5,29.57 23.62,32.69 26.7,32.69 v1(27.56,33.55)
P80: length 33.5
  TOP w0.196: J1.57 9.74,35.2 9.47,35.46 9.47,38.12 9.81,38.46 15.39,38.46 17.04,36.8 21.54,36.8 30.35,45.62 32.9,45.62 J4.15
P81: length 24
  TOP w0.196: J4.2 30.54,30.2 27.93,30.2 24.18,33.96 16.81,33.96 14.77,36 J1.59
P82: length 23.3
  TOP w0.196: J1.61 14.97,36.8 17.07,34.7 24.25,34.7 27.3,31.65 J4.4
P83: length 23.8
  TOP w0.196: J1.63 15.28,37.6 17.17,35.71 24.05,35.71 27.02,32.75 28.53,32.75 29.98,34.19 J4.6
P84: length 25.2
  TOP w0.196: J1.58 v1(8.25,35.2)
  BOTTOM w0.196: v1(8.25,35.2) 8.96,35.2 9.4,35.64 28.19,35.64 29.31,36.75 31.6,36.75 J4.8
P85: length 25.9
  TOP w0.196: J1.60 v1(8.25,36)
  BOTTOM w0.196: J4.10 29.9,39.27 27.1,36.47 8.72,36.47 v1(8.25,36)
P90: length 62.2
  TOP w0.196: v1(29.54,18.52) 29.97,18.95 37.72,18.95 v1(37.82,19.05) ; J1.14 9.04,17.6 v1(9.35,17.91) ; v1(41.07,27.46) 41.07,34.52 v1(37.64,37.95)
  BOTTOM w0.196: v1(37.82,19.05) 41.07,22.3 v1(41.07,27.46) ; J4.12 32.9,40.54 36.47,40.54 37.64,39.37 v1(37.64,37.95) ; v1(29.54,18.52) 28.02,17 20.54,17 19.63,17.91 v1(9.35,17.91)
P91: length 62.9
  TOP w0.196: v1(37.8,36.37) 40.41,33.76 40.41,27.15 v1(40.45,27.1) ; v1(29.36,19.38) 29.36,20.42 30.51,21.56 v1(37.67,21.56) ; J1.16 8.62,18.4 8.86,18.64 v1(9.4,18.64)
  BOTTOM w0.196: J4.14 32.87,43.1 35.43,43.1 38.23,40.31 38.23,36.8 v1(37.8,36.37) ; v1(37.67,21.56) 40.45,24.35 v1(40.45,27.1) ; v1(9.4,18.64) 19.71,18.64 20.78,17.58 27.56,17.58 v1(29.36,19.38)
P92: length 48.2
  TOP w0.196: J4.16 30.61,46.89 21.1,37.38 17.46,37.38 15.77,39.07 9.6,39.07 8.9,38.36 8.9,27.58 8.98,27.5 8.98,22.54 8.46,22.02 8.46,19.58 8.07,19.2 J1.18
P93: length 71.8
  TOP w0.196: v1(4.34,57.35) 4.29,57.3 4.29,21.01 5.3,20 J1.20 ; v1(26.04,59.68) 23.86,59.68 22.2,61.34 v1(20.04,61.34)
  BOTTOM w0.196: J5.8 27.21,60.86 v1(26.04,59.68) ; v1(20.04,61.34) 18.49,62.89 11.1,62.89 9.35,61.14 8.39,61.14 8.39,61.14 7.47,61.14 6.3,59.97 6.3,58.72 6.29,58.71 6.29,58.56 5.08,57.35 v1(4.34,57.35)
P94: length 79.3
  TOP w0.196: v1(20.47,61.93) 22.48,61.93 24.15,60.26 25.59,60.26 26.72,61.39 v1(26.72,62.64) ; v1(4.37,58.27) 3.71,57.61 3.71,20.77 4.09,20.39 4.09,16.54 5.42,15.2 J1.8
  BOTTOM w0.196: v1(20.47,61.93) 18.93,63.46 10.86,63.46 9.11,61.72 7.23,61.72 5.71,60.2 5.71,58.8 5.18,58.27 v1(4.37,58.27) ; v1(26.72,62.64) 27.48,63.4 J5.10
P95: length 74.7
  TOP w0.196: J1.22 5.31,20.8 4.87,21.25 4.87,57.06 5.08,57.27 v1(5.08,59.13) ; J5.12 28.78,65.94 26.1,63.26 26.1,61.59 25.35,60.83 24.56,60.83 22.62,62.78 v1(22.62,63.59)
  BOTTOM w0.196: v1(5.08,59.13) 5.08,60.48 6.89,62.29 8.8,62.29 10.59,64.08 22.13,64.08 v1(22.62,63.59)
XRES: length 87.1
  TOP w0.196: J1.2 4.01,12.8 1.74,15.07 1.74,63.01 7.75,69.01 22.15,69.01 23.06,68.1 v1(26.75,68.1)
  BOTTOM w0.196: v1(26.75,68.1) 27.13,68.48 J5.14

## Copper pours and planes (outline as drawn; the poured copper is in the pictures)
+3V3_OUT on TOP: 13.21,67.84 17.65,67.84 17.91,67.59 17.91,62.87 19.66,61.11 22.89,61.11 25.53,58.47 25.53,56.9 25.4,56.77 18.54,56.77 12.42,62.89 6.73,62.89 6.48,63.15 6.48,63.91 7.37,63.91 7.49,63.78 9.14,63.78
+3V3_OUT on TOP: 10.41,13.08 13.84,13.08 15.62,11.3 18.06,11.3 18.16,11.2 18.16,7.11 17.78,6.73 11.81,6.73 11.68,6.86 11.68,10.67 11.25,11.1 11.25,12.55 10.54,11.84 10.54,11.3 10.19,11.66 10.19,12.85
+3V3_OUT on BOTTOM: 32.31,59.23 27.38,59.23 26.42,58.27 24.64,58.27 24.03,57.66 24.03,56.01 24.49,55.55 28.55,55.55 30.43,57.43 32.36,57.43 32.59,57.66 32.59,58.95
+3V3_OUT on BOTTOM: 17.25,69.09 7.9,69.09 1.02,62.2 1.02,7.98 5.84,3.15 15.52,3.15 18.24,5.87 18.24,7.98 17.81,8.41 7.47,8.41 3.81,12.06 3.81,59.05 7.24,62.48 8.69,62.48 10.35,64.15 17.67,64.15 18.03,64.52 18.03,68.3
+5V0_IN on TOP: 17.91,14 15.88,14 15.49,13.62 15.49,12.22 15.88,11.84 17.91,11.84 18.16,12.09 18.16,13.74
+5V0_IN on TOP: 15.57,27.97 17.37,27.97 17.78,27.56 17.78,26.32 17.81,26.29 17.81,22.61 17.91,22.51 17.91,20.85 17.65,20.6 17.4,20.6 15.37,20.6 15.04,20.93 15.04,27.43
+5V0_IN on BOTTOM: 32.94,49.86 22.45,39.37 10.46,39.37 7.67,36.58 7.67,29.49 11.94,25.22 11.94,23.39 13.21,22.12 16.81,22.12 17.17,21.77 17.17,20.55 17.04,20.42 10.21,20.42 9.35,21.29 9.35,23.37 8.99,23.72 8.31,23.72 6.6,22.02 6.6,14.86 8.23,13.23 16.81,13.23 17.27,12.78 17.27,10.77 16.08,9.58 7.19,9.58 4.34,12.42 4.34,39.85 5.77,41.27 20.85,41.27 29.72,50.14 29.72,55.75 30.48,56.52 32.51,56.52 32.94,56.08
AGND on TOP: 49.38,72.72 49.2,72.9 50.04,72.9 51.94,70.99 51.94,51.66 50.57,50.29 31.47,50.29 23.34,42.17 23.34,43.59 21.89,45.03 21.44,45.03 21.03,44.63 21.03,44.02 21.84,44.02 22.66,43.21 22.66,41.48 22.07,40.89 6.27,40.89 5.89,41.27 5.89,51 6.35,51.46 11.81,51.46 19.38,59.03 19.38,61.85 20.14,62.61 21.59,62.61 21.97,62.99 21.97,64.47 22.5,63.93 24.74,63.93 25.25,64.44 22.38,64.44 21.97,64.85 21.97,66.14 22.78,66.95 26.77,66.95 27.66,67.84 27.66,69.11 26.75,70.03 20.47,70.03 20.19,70.31 20.19,72.31 20.78,72.9 47.68,72.9 48.39,72.19 48.39,64.97 47.88,64.47 45.95,64.47 46.91,63.5 49.38,63.5 ; 34 cut-outs
AGND on GND: 20.78,72.9 50.04,72.9 51.94,70.99 51.94,51.69 50.55,50.29 31.47,50.29 22.07,40.89 6.27,40.89 5.89,41.27 5.89,51 6.35,51.46 11.81,51.46 19.38,59.03 19.38,61.85 20.14,62.61 21.59,62.61 21.97,62.99 21.97,66.12 22.81,66.95 26.77,66.95 27.66,67.84 27.66,69.14 26.8,70 20.5,70 20.19,70.31 20.19,72.31
AGND on GND1: 25.53,72.9 50.04,72.9 51.94,70.99 51.94,51.69 50.55,50.29 31.47,50.29 22.07,40.89 6.27,40.89 5.89,41.27 5.89,51 6.35,51.46 11.79,51.46 19.3,58.98 19.3,59.92 22.61,63.22 22.61,66.78 24,68.17 24,71.37
GND_SIGNAL on TOP: 53.98,3.56 53.24,1.76 51.44,1.02 3.56,1.02 1.76,1.76 1.02,3.56 1.02,72.44 1.76,74.24 3.56,74.98 51.44,74.98 53.24,74.24 53.98,72.44 ; 67 cut-outs
GND_SIGNAL on BOTTOM: 1.02,72.44 1.76,74.24 3.56,74.98 51.44,74.98 53.23,74.24 53.98,72.44 53.98,3.56 53.23,1.76 51.44,1.02 3.56,1.02 1.76,1.76 1.02,3.56 1.02,5.97 1.45,6.4 2.18,6.4 1.45,7.14 1.07,7.14 1.02,7.09 ; 64 cut-outs
GND_SIGNAL on GND: 1.02,72.44 1.76,74.24 3.56,74.98 51.44,74.98 53.24,74.24 53.98,72.44 53.98,3.56 53.24,1.76 51.44,1.02 3.56,1.02 1.76,1.76 1.02,3.56
GND_SIGNAL on GND1: 1.02,72.44 1.76,74.24 3.56,74.98 51.43,74.98 53.23,74.24 53.97,72.44 53.97,3.56 53.23,1.76 51.43,1.02 3.56,1.02 1.76,1.76 1.02,3.56

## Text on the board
BOTTOM: BOTTOM SIDE
Ref Des/Assembly Bottom: ASSEMBLY BOTTOM
Board Geometry/Soldermask Bottom: SOLDERMASK BOTTOM
Ref Des/Silkscreen Bottom: QR CODE | BARCODE | REV 03 | 600-60702-01 | SILKSCREEN BOTTOM
TOP: TOP SIDE
Ref Des/Assembly Top: ASSEMBLY TOP
Board Geometry/Soldermask Top: SOLDERMASK TOP
Ref Des/Silkscreen Top: AGND | GND | 5V0.IN | PSOC C3M5 INTERFACE BOARD | + | SILKSCREEN TOP
GND: L02_GND
GND1: L03_GND1
PASTEMASK_TOP: SOLDERPASTE TOP
PAGE_OUTLINE: SOLDERPASTE BOTTOM
DIMENSION: X4
User.6: GOLDMASK TOP
User.7: GOLDMASK BOTTOM
User.12: UNITS ARE IN MM [INCH]
User.17: C. FILL ALL THRU VIAS USING NON-CONDUCTIVE EPOXY AND OVERPLATE WITH COPPER, .005 [.0002] | MINIMUM THICKNESS. DIMPLE DEPTH IN BGA PADS SHALL BE .025 [.001] MAXIMUM. THE PRESENCE | OF WRAP PLATING SHALL BE VISUALLY EVIDENT IN ALL QUALITY CONFORMANCE MICROSECTIONS; NO | MINIMUM MEASUREMENT REQUIRED.
User.21: SANTHOSH R | GURRAL | 19/08/24
User.22: 2
User.39: PROJECT: | DRAWN BY: | LAYER: | DWG NO: | REV: | DATE: | Am Campeon 1-15 | Infineon Technologies AG | 85579 NEUBIBERG - GERMANY | PSOC C3M5 INTERFACE BOARD | ECAD | 620-60702-01 | 03 | 19/08/2024
User.45: FIGURE | FINISHED_SIZE | 10.0 | 33.07 | 39.76 | 62.99 | 50.0 | DRILLED_SIZE | - | DRILL CHART: TOP to BOTTOM | ALL UNITS ARE IN MILS | FINISHED_TOL | +3.0/-3.0 | +2.0/-2.0 | DRILLED_TOL | PLATED | NON-PLATED | QTY | 200 | 2 | 80 | 4
